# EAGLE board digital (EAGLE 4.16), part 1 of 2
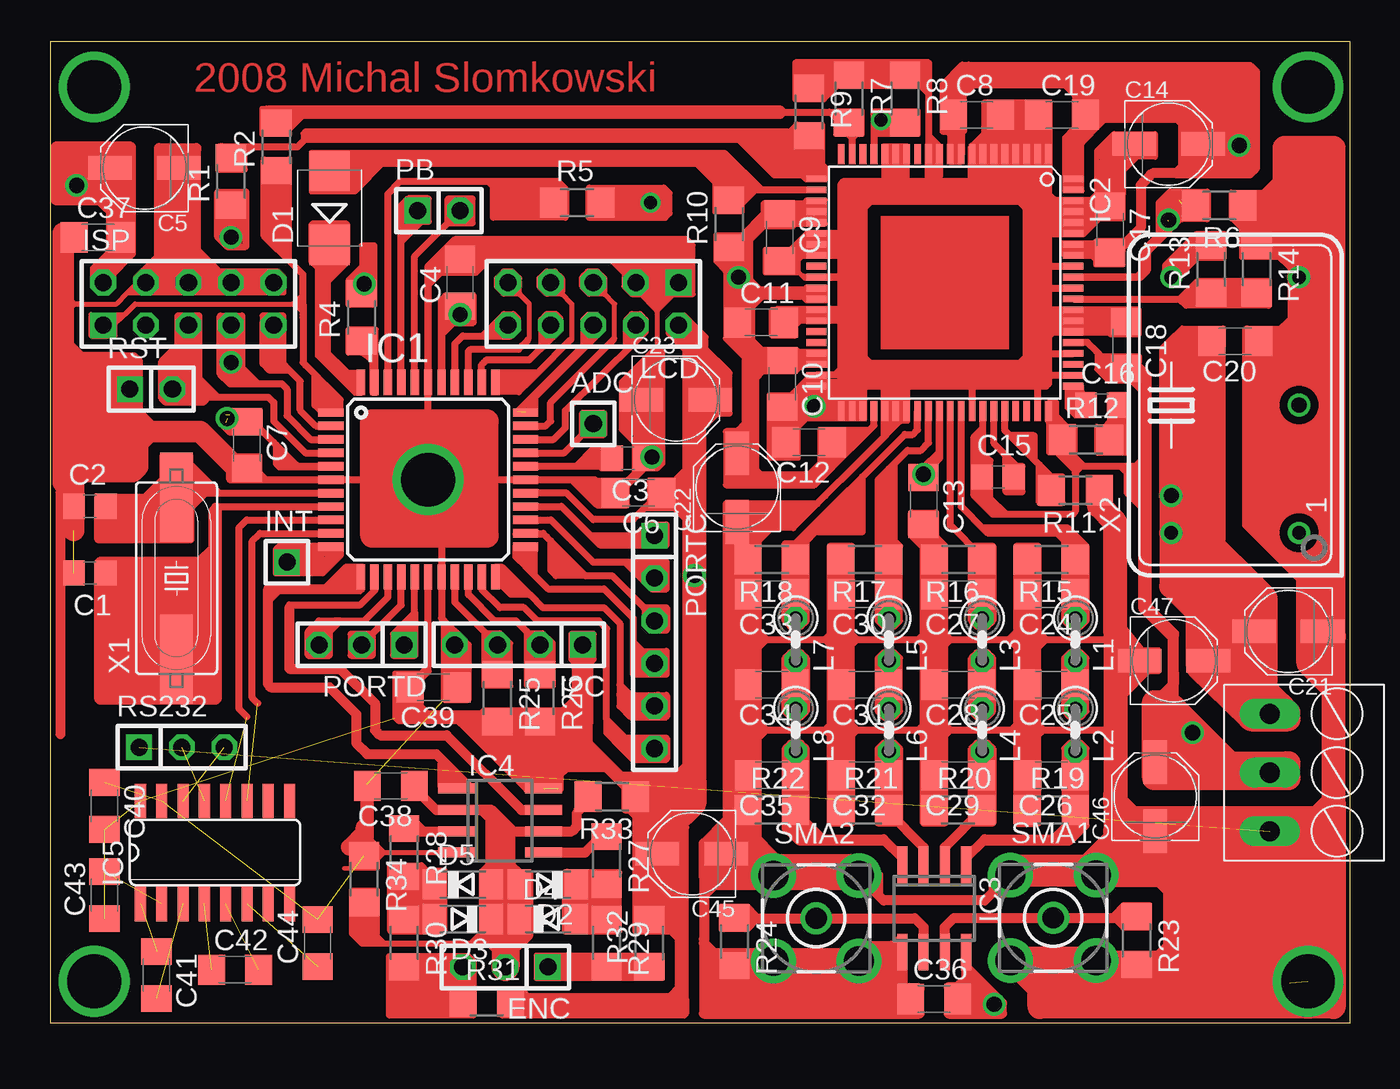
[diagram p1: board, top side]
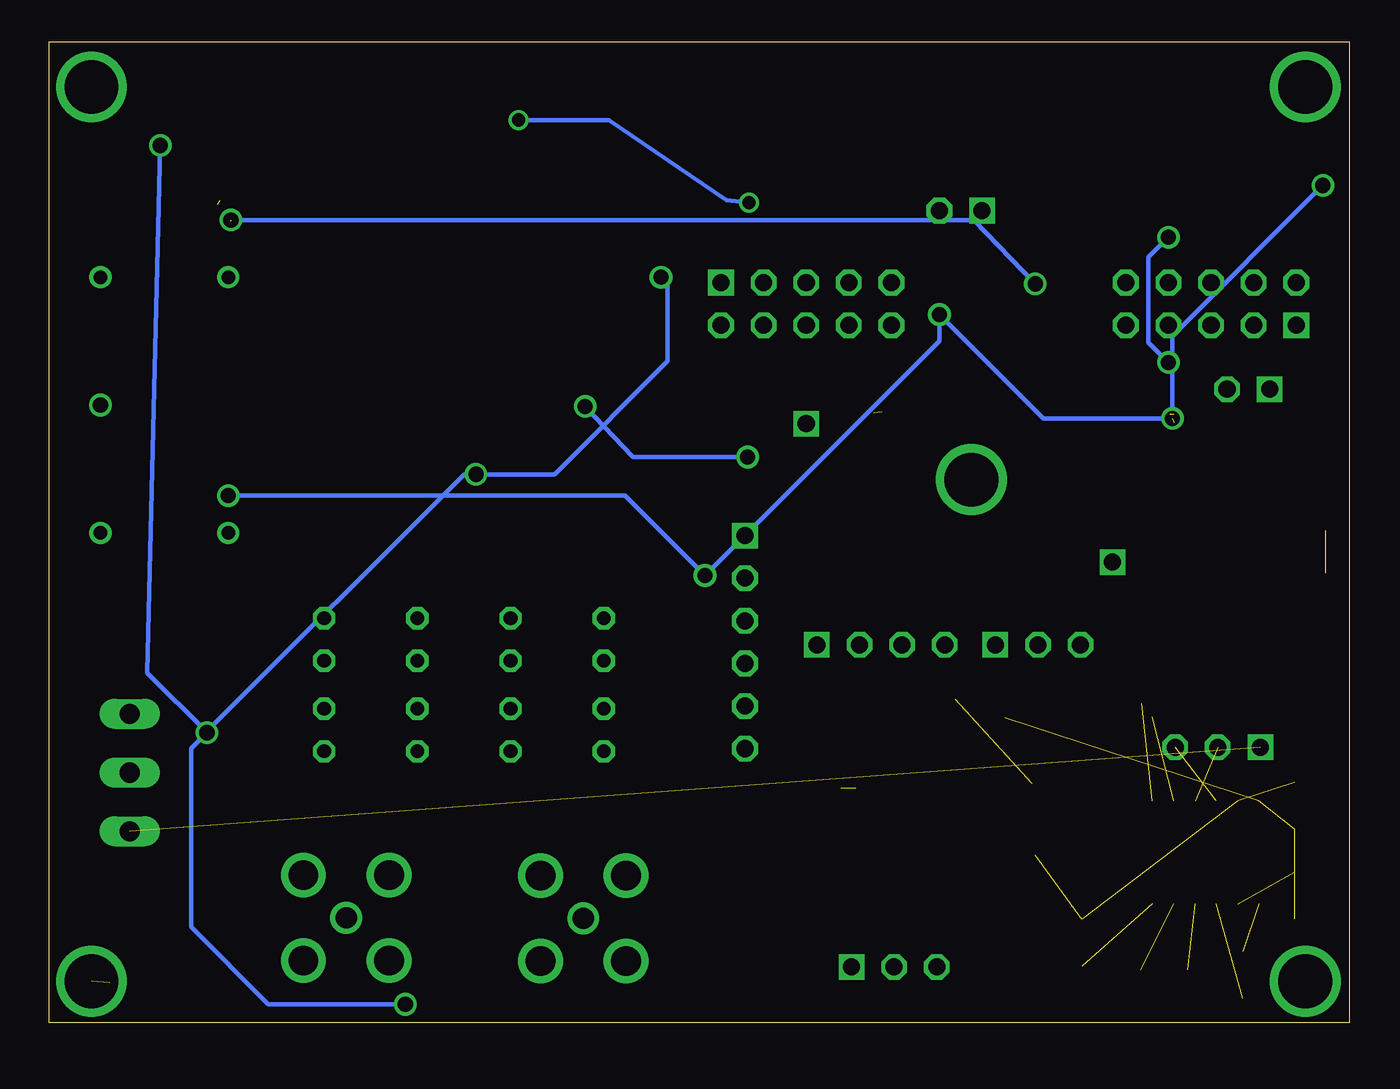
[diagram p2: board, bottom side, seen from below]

Size 77.51 x 58.47 mm. Coordinates in mm from the lower left corner, seen from the top.
Outline: 0,0 77.51,0 77.51,58.47 0,58.47 0,0
Copper layers (1*16): Top 0.035mm / dielectric 1.5mm / Bottom 0.035mm
Design rules "default": minimum track width 10mil, minimum drill 24mil, track to track 8mil, track to pad 8mil, pad to pad 8mil, via to via 8mil, smd to smd 8mil, copper to edge 40mil, drill to drill 8mil, minimum pad ring 10mil, minimum via ring 8mil, stop-mask expansion 4mil, vias tented up to drill 0mil, thermal gap 10mil

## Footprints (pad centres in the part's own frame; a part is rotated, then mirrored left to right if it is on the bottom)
1X01 = drill 1.016 square: 1 0,0
C0805 = smd 1.3 x 1.5: 1 -0.95,0; 2 0.95,0
C1206 = smd 1.6 x 1.8: 1 -1.4,0; 2 1.4,0
PANASONIC_C = smd 2.6 x 1.4: + 2.05,0; - -2.05,0
SMB = smd 2.4 x 2.4: A 2.2,0; C -2.2,0
SOD80C = smd 1.4 x 1.8: A 1.7,0; C -1.7,0
1X03 = drill 1.016 square: 1 -2.54,0 | drill 1.016 octagon: 2 0,0; 3 2.54,0
1X04 = drill 1.016 square: 1 -3.81,0 | drill 1.016 octagon: 2 -1.27,0; 3 1.27,0; 4 3.81,0
TQFP44 = smd 1.5 x 0.5: 1 -5.8,4; 2 -5.8,3.2; 3 -5.8,2.4; 4 -5.8,1.6; 5 -5.8,0.8; 6 -5.8,0; 7 -5.8,-0.8; 8 -5.8,-1.6; 9 -5.8,-2.4; 10 -5.8,-3.2; 11 -5.8,-4; 23 5.8,-4; 24 5.8,-3.2; 25 5.8,-2.4; 26 5.8,-1.6; 27 5.8,-0.8; 28 5.8,0; 29 5.8,0.8; 30 5.8,1.6; 31 5.8,2.4; 32 5.8,3.2; 33 5.8,4 | smd 0.5 x 1.5: 12 -4,-5.8; 13 -3.2,-5.8; 14 -2.4,-5.8; 15 -1.6,-5.8; 16 -0.8,-5.8; 17 0,-5.8; 18 0.8,-5.8; 19 1.6,-5.8; 20 2.4,-5.8; 21 3.2,-5.8; 22 4,-5.8; 34 4,5.8; 35 3.2,5.8; 36 2.4,5.8; 37 1.6,5.8; 38 0.8,5.8; 39 0,5.8; 40 -0.8,5.8; 41 -1.6,5.8; 42 -2.4,5.8; 43 -3.2,5.8; 44 -4,5.8
TQFP80-917 = smd 1.2 x 0.4: 1 -7.65,4.905; 2 -7.65,4.255; 3 -7.65,3.605; 4 -7.65,2.955; 5 -7.65,2.305; 6 -7.65,1.655; 7 -7.65,1.005; 8 -7.65,0.355; 9 -7.65,-0.295; 10 -7.65,-0.945; 11 -7.65,-1.595; 12 -7.65,-2.245; 13 -7.65,-2.895; 14 -7.65,-3.545; 15 -7.65,-4.195; 16 -7.65,-4.845; 17 -7.65,-5.495; 18 -7.65,-6.145; 19 -7.65,-6.795; 20 -7.65,-7.445; 41 7.65,-7.445; 42 7.65,-6.795; 43 7.65,-6.145; 44 7.65,-5.495; 45 7.65,-4.845; 46 7.65,-4.195; 47 7.65,-3.545; 48 7.65,-2.895; 49 7.65,-2.245; 50 7.65,-1.595; 51 7.65,-0.945; 52 7.65,-0.295; 53 7.65,0.355; 54 7.65,1.005; 55 7.65,1.655; 56 7.65,2.305; 57 7.65,2.955; 58 7.65,3.605; 59 7.65,4.255; 60 7.65,4.905 | smd 0.4 x 1.2: 21 -6.175,-8.92; 22 -5.525,-8.92; 23 -4.875,-8.92; 24 -4.225,-8.92; 25 -3.575,-8.92; 26 -2.925,-8.92; 27 -2.275,-8.92; 28 -1.625,-8.92; 29 -0.975,-8.92; 30 -0.325,-8.92; 31 0.325,-8.92; 32 0.975,-8.92; 33 1.625,-8.92; 34 2.275,-8.92; 35 2.925,-8.92; 36 3.575,-8.92; 37 4.225,-8.92; 38 4.875,-8.92; 39 5.525,-8.92; 40 6.175,-8.92; 61 6.175,6.38; 62 5.525,6.38; 63 4.875,6.38; 64 4.225,6.38; 65 3.575,6.38; 66 2.925,6.38; 67 2.275,6.38; 68 1.625,6.38; 69 0.975,6.38; 70 0.325,6.38; 71 -0.325,6.38; 72 -0.975,6.38; 73 -1.625,6.38; 74 -2.275,6.38; 75 -2.925,6.38; 76 -3.575,6.38; 77 -4.225,6.38; 78 -4.875,6.38; 79 -5.525,6.38; 80 -6.175,6.38
SO08 = smd 0.6 x 2.2: 1 -1.905,-2.6; 2 -0.635,-2.6; 3 0.635,-2.6; 4 1.905,-2.6; 5 1.905,2.6; 6 0.635,2.6; 7 -0.635,2.6; 8 -1.905,2.6
SO16 = smd 0.66 x 2.032: 1 -4.445,-3.073; 2 -3.175,-3.073; 3 -1.905,-3.073; 4 -0.635,-3.073; 5 0.635,-3.073; 6 1.905,-3.073; 7 3.175,-3.073; 8 4.445,-3.073; 9 4.445,3.073; 10 3.175,3.073; 11 1.905,3.073; 12 0.635,3.073; 13 -0.635,3.073; 14 -1.905,3.073; 15 -3.175,3.073; 16 -4.445,3.073
2X05 = drill 1.016 square: 1 -5.08,-1.27 | drill 1.016 octagon: 2 -5.08,1.27; 3 -2.54,-1.27; 4 -2.54,1.27; 5 0,-1.27; 6 0,1.27; 7 2.54,-1.27; 8 2.54,1.27; 9 5.08,-1.27; 10 5.08,1.27
0207/2V = drill 0.813 octagon: 1 -1.27,0; 2 1.27,0
1X02 = drill 1.016 square: 1 -1.27,0 | drill 1.016 octagon: 2 1.27,0
1X06 = drill 1.016 square: 1 -6.35,0 | drill 1.016 octagon: 2 -3.81,0; 3 -1.27,0; 4 1.27,0; 5 3.81,0; 6 6.35,0
R1206 = smd 1.6 x 1.803: 1 -1.422,0; 2 1.422,0
BU-SMA-V = drill 1.27 round: 1 0,0 | drill 1.778 round: 2 -2.55,2.55; 3 2.55,2.55; 4 2.55,-2.55; 5 -2.55,-2.55
RIACON-3 = drill 1.2 long: P$1 0,-3.5; P$2 0,0; P$3 0,3.5
HC49UP = smd 5.334 x 1.93: 1 -4.826,0; 2 4.826,0
DIL14S = drill 0.813 round: 1 -7.62,-3.81; 7 7.62,-3.81; 8 7.62,3.81; 14 -7.62,3.81

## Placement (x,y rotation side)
ADC  [1X01]  32.38,35.71 0 top
C1  22p  [C0805]  2.38,26.82 180 top
C2  22p  [C0805]  2.38,30.79 0 top
C3  100n  [C0805]  34.44,33.65 180 top
C4  [C1206]  24.44,44.13 90 top
C5  47u  [PANASONIC_C]  5.63,50.95 180 top
C6  [C1206]  35.08,31.59 180 top
C7  [C1206]  11.74,34.44 270 top
C8  100n  [C1206]  55.24,54.13 0 top
C9  [C1206]  43.49,46.83 270 top
C10  [C1206]  43.65,38.09 270 top
C11  [C1206]  42.38,41.75 0 top
C12  [C1206]  45.24,34.6 180 top
C13  [C1206]  52.07,31.11 270 top
C14  47u  [PANASONIC_C]  66.67,52.38 0 top
C15  10n  [C0805]  56.51,32.54 0 top
C16  10n  [C0805]  62.7,36.82 0 top
C17  [C1206]  63.18,47.3 270 top
C18  [C1206]  64.13,40.4 270 top
C19  [C1206]  60.32,54.13 0 top
C20  100n  [C1206]  70.64,40.63 180 top
C21  47u  [PANASONIC_C]  73.81,23.33 180 top
C22  47u  [PANASONIC_C]  40.95,31.9 90 top
C23  47u  [PANASONIC_C]  37.3,37.14 0 top
C24  10p  [C1206]  59.68,25.55 180 top
C25  33p  [C1206]  59.68,20.15 180 top
C26  10p  [C1206]  59.68,14.76 180 top
C27  10p  [C1206]  54.13,25.55 180 top
C28  33p  [C1206]  54.13,20.16 180 top
C29  10p  [C1206]  54.13,14.76 180 top
C30  10p  [C1206]  48.57,25.55 180 top
C31  33p  [C1206]  48.57,20.15 180 top
C32  10p  [C1206]  48.57,14.76 180 top
C33  10p  [C1206]  43.02,25.55 180 top
C34  33p  [C1206]  43.02,20.15 180 top
C35  10p  [C1206]  43.02,14.76 180 top
C36  100n  [C1206]  52.7,1.42 0 top
C37  100n  [C1206]  2.85,46.82 0 top
C38  100n  [C1206]  20.31,14.12 180 top
C39  100n  [C1206]  22.85,20 180 top
C40  100n  [C1206]  3.25,12.93 270 top
C41  1u  [C1206]  6.34,2.85 270 top
C42  1u  [C1206]  11.03,3.17 0 top
C43  1u  [C1206]  3.25,7.61 90 top
C44  1u  [C1206]  15.95,4.76 90 top
C45  47u  [PANASONIC_C]  38.25,10.07 180 top
C46  47u  [PANASONIC_C]  65.88,13.49 90 top
C47  47u  [PANASONIC_C]  66.99,21.58 0 top
D1  [SMB]  16.66,48.57 90 top
D2  [SOD80C]  29.68,8.25 180 top
D3  [SOD80C]  24.6,6.19 180 top
D4  [SOD80C]  29.68,6.19 0 top
D5  [SOD80C]  24.6,8.25 0 top
ENC  [1X03]  27.14,3.33 180 top
I2C  [1X04]  27.93,22.54 180 top
IC1  MEGA32-A  [TQFP44]  22.54,32.38 0 top
IC2  AD9854  [TQFP80-917]  54.6,44.13 270 top
IC3  FIN1028  [SO08]  52.7,6.82 180 top
IC4  LM358D  [SO08]  26.82,12.06 270 top
IC5  MAX232  [SO16]  9.84,10.15 0 top
INT  [1X01]  14.12,27.46 0 top
ISP  [2X05]  8.25,42.86 0 top
L1  1u  [0207/2V]  61.11,22.85 270 top
L2  1u  [0207/2V]  61.11,17.46 270 top
L3  1u  [0207/2V]  55.56,22.85 270 top
L4  1u  [0207/2V]  55.56,17.46 270 top
L5  1u  [0207/2V]  50,22.85 270 top
L6  1u  [0207/2V]  50,17.46 270 top
L7  1u  [0207/2V]  44.44,22.85 270 top
L8  1u  [0207/2V]  44.44,17.46 270 top
LCD  [2X05]  32.38,42.86 180 top
PB  [1X02]  23.17,48.41 0 top
PORTC  [1X06]  36.03,22.69 270 top
PORTD  [1X03]  18.57,22.54 180 top
R1  [R1206]  10.79,50.16 90 top
R2  [R1206]  13.49,52.22 90 top
R4  [R1206]  18.57,42.06 90 top
R5  [R1206]  31.43,48.89 0 top
R6  [R1206]  69.69,48.73 180 top
R7  [R1206]  47.62,55.08 270 top
R8  [R1206]  50.95,55.08 270 top
R9  [R1206]  45.24,54.29 270 top
R10  [R1206]  40.48,47.62 90 top
R11  3k9  [R1206]  61.11,31.74 180 top
R12  1k3  [R1206]  61.75,34.76 0 top
R13  [R1206]  69.21,44.92 90 top
R14  [R1206]  71.91,44.92 270 top
R15  [R1206]  59.68,27.62 180 top
R16  [R1206]  54.13,27.62 180 top
R17  [R1206]  48.57,27.62 180 top
R18  [R1206]  43.02,27.62 180 top
R19  200  [R1206]  59.68,12.69 0 top
R20  200  [R1206]  54.13,12.69 0 top
R21  200  [R1206]  48.57,12.69 0 top
R22  200  [R1206]  43.02,12.69 0 top
R23  100k  [R1206]  64.77,4.92 270 top
R24  100k  [R1206]  40.79,4.84 270 top
R25  [R1206]  26.66,19.36 270 top
R26  4k7  [R1206]  29.2,19.36 270 top
R27  4k7  [R1206]  33.17,9.68 270 top
R28  4k7  [R1206]  21.11,10.15 270 top
R29  4k7  [R1206]  33.17,4.76 270 top
R30  4k7  [R1206]  21.11,4.76 270 top
R31  1M  [R1206]  26.03,1.26 0 top
R32  1M  [R1206]  35.71,4.76 90 top
R33  4k7  [R1206]  33.49,13.49 180 top
R34  2k2  [R1206]  18.73,8.57 270 top
RS232  [1X03]  7.85,16.42 0 top
RST  [1X02]  6.03,37.78 0 top
SMA1  [BU-SMA-V]  59.8,6.26 0 top
SMA2  [BU-SMA-V]  45.67,6.23 0 top
U$2  RIACON-3  [RIACON-3]  72.7,14.92 180 top
X1  16MHz  [HC49UP]  7.54,26.5 90 top
X2  [DIL14S]  70.64,36.82 90 top

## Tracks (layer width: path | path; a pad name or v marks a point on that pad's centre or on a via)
GND  (1 unrouted)
N$1
  Top 0.406: R9.2 45.4,52.86 45.69,52.89 IC2.21 | 15.39,52.86 14.76,52.22 11.98,52.22 | R1.2 10.16,52.22 10.31,52.22 | 10.31,52.22 11.98,52.22 | 10.31,52.22 10.08,52.22 10.08,50.87 11.58,50.87 11.58,51.83 11.98,52.22
  Top 0.813: R9.2 15.4,52.86 15.39,52.86
N$2
  Top 1.27: 72.46,48.41 72.54,48.41 73.58,47.38
N$3
  Top 0.406: R13.1 69.05,43.49 68.71,43.15 IC2.69
  Top 1.422: R14.2 71.43,43.49 R14.2 R13.1
N$4
  Top 0.406: IC1.44 18.01,38.18 17.46,38.73
  Top 0.61: 17.62,47.46 17.62,45.4 16.35,44.13
  Top 0.813: 17.46,38.73 16.35,39.84 16.35,44.13 16.35,45.4 16.03,45.71 D1.C
N$5
  Top 0.406: R10.2 41.11,49.05 41.72,49.65 IC2.22
  Top 0.813: 41.11,49.05 41.11,50.63 40.32,51.43 17.3,51.43 16.66,50.79 D1.A
N$6
  Top 1.27: R12.2 63.18,34.6 63.65,34.6 C16.2
N$7  (via drill 0.9)  (2 unrouted)
  Top 0.254: R4.2 18.5,43.48 18.49,43.49 18.97,43.97 v18.73,44.05
  Top 0.406: R6.2 68.18,48.65 67.3,48.65 67.3,48.17 65.16,46.03 65.16,44.84 64.77,44.45 IC2.71 65.01,44.45 65.4,44.84 65.4,45.95 67.46,48.02 67.46,48.81 v66.67,47.86
  Top 0.61: R4.2 18.57,43.57 18.49,43.65 19.04,44.21 19.04,44.36
  Top 0.813: 19.04,44.36 19.04,44.68
  Top 1.016: 67.3,49.05 66.99,49.05 66.91,48.97 | 66.67,47.78 66.67,48.73
  Bottom 0.254: v66.67,47.86 22.38,47.86 v18.73,44.05
N$8
  Top 1.016: X2.8 66.83,44.52 68.5,46.19 69.21,46.19 69.29,46.27 R13.2
N$9
  Top 0.61: 3.96,47.46 3.96,48.02 2.93,49.05 0.31,49.05 0.31,52.22 4.84,52.22 4.84,45.87 3.49,44.52
N$10
  Top 0.305: 17.77,44.21 17.77,42.78 19.36,42.78 19.36,46.35 18.57,46.35 18.57,45.08 | 17.77,44.21 17.77,44.28 | 17.77,44.28 18.49,44.84 18.41,44.84 18.57,45 18.57,45.08 | 17.77,44.21 17.77,44.28 | 17.77,44.28 18.57,45.08
N$11
  Top 0.61: R27.1 32.7,11.58 33.33,11.58 31.9,10.15 IC4.5
N$12
  Top 0.406: 59.69,32.54 | R11.2 59.69,32.54 | IC2.56 56.91,35.31 59.69,32.54
N$13
  Top 1.27: 0.79,32.22 0.79,47.06
N$14
  Top 0.406: IC2.55 56.26,34.53 57.62,33.17 57.62,32.7 C15.2 | C15.2 | C15.2
N$15
  Top 1.27: 55.56,20.15 L3.2 | 55.56,20.15 | 55.56,20.15 | C28.1 55.56,20.15 | 55.56,20.15 L4.1
N$16
  Top 0.61: R28.1 21.27,11.42 IC4.3
N$17
  Top 0.406: X1.2 7.62,32.85 7.62,31.58 7.78,31.58 IC1.7
  Top 1.27: C2.2 7.62,30.79 7.62,31.58 | 7.62,31.58
N$18
  Top 0.406: IC1.8 9.83,30.78 9.84,30.47
  Top 0.813: 7.46,26.82 C1.1 | 7.46,26.82 9.2,26.82 9.84,27.46 9.84,27.62 | 9.84,27.62 9.84,28.25 | 9.84,28.25 9.84,30.47 | 7.46,26.82 7.38,26.82 5.31,26.43 X1.1 | 9.84,27.62 9.84,19.36 3.01,19.36 3.01,27.38 8.96,27.38 9.84,28.25
N$19  (1 unrouted)
  Top 0.406: IC1.10 12.51,29.18 12.06,28.73 12.06,19.36 12.38,19.04
N$20  (1 unrouted)
  Top 0.406: IC1.9 11.72,29.98 11.27,29.52 11.27,18.73 11.74,18.25
N$21
  Top 0.406: C3.2 33.33,33.17 33.02,33.18 IC1.29
N$23
  Top 0.406: IC1.19 24.14,25.06 I2C.3
  Top 1.422: R25.1 I2C.3
N$24  (via drill 0.8)
  Top 0.406: IC2.17 49.11,54.27 49.53,53.17 49.53,53.65 | R8.2 50.8,53.66 50.8,53.65 49.53,53.65 | v49.53,53.81 49.53,53.65
  Top 1.422: R5.2 v35.79,48.89
  Bottom 0.254: v35.79,48.89 37.14,49.05 44.13,53.81 v49.53,53.81
N$25
  Top 0.406: R4.1 18.42,40.8 18.41,40.79 19.34,39.87 IC1.43
N$26
  Top 0.406: IC1.42 20.14,49.43 20.87,50.16 25.87,50.16 | 25.87,50.16 26.11,50.16 27.06,49.21 28.73,49.21 29.05,48.89 R5.1 | 30.71,49.68 26.59,49.68 | 30.71,49.68 30.71,48.02 26.43,48.02 26.43,49.76 | 25.87,50.16 30.24,50.16 30.71,49.68
N$27
  Top 0.406: C16.1 61.75,37.14 60.98,37.91 IC2.61
N$28
  Top 0.406: 58.73,22.22 59.37,22.85 58.89,23.33 58.89,28.41 57.62,28.41 57.62,23.33 57.15,22.85 57.78,22.22
N$29
  Top 0.406: R16.1 55.55,27.77 55.56,27.77 53.66,29.67 IC2.51
  Top 1.27: C27.1 55.53,25.42 55.56,25.39 L3.1
  Top 1.422: R16.1 55.55,25.56 55.56,25.55 | C27.1 55.56,25.55 | 55.56,25.55
N$30
  Top 0.406: IC2.49 52.36,34.58 51.91,34.12 51.11,34.12 50,33.01 50,32.85
  Top 0.61: R17.1 49.99,27.46 50,27.46 50,32.85
  Top 1.27: 50,25.55 L5.1
  Top 1.422: 50,27.46 50,25.55 | C30.1 50,25.55 | 50,25.55
N$31
  Top 0.406: IC2.48 51.71,35.36 51.43,35.08 50.95,35.08 44.45,28.57 44.45,27.46 44.44,27.46 R18.1
  Top 1.27: L7.1 44.45,25.55
  Top 1.422: 44.45,25.55 | 44.45,25.55 C33.1 | 44.45,27.46 44.45,25.55
N$32
  Top 1.27: 61.11,20.15 L2.1 | 61.11,20.15 L1.2
  Top 1.422: 61.11,20.15 | C25.1 61.11,20.15 | 61.11,20.15
N$33
  Top 0.61: R19.2 61.42,12.53 59.84,10.95 55.72,10.95 54.61,9.84 | 54.61,9.84 | IC3.1 54.61,9.84
  Top 1.27: 61.11,14.76 L2.2
  Top 1.422: 61.11,14.76 | 61.11,14.76 | 61.11,14.76 C26.1 | R19.2 61.11,14.75 61.11,14.76
N$34
  Top 1.016: L6.1 50,20.08 49.92,20.15 C31.1 50,20.15 | 50,20.15 L5.2 | 50,20.15
N$35
  Top 0.61: IC3.3 52.07,10.47 49.99,12.54 R21.2
  Top 1.27: 50,14.76 L6.2
  Top 1.422: 50,14.76 | 50,14.76 | 50,14.76 C32.1 | R21.2 49.99,14.75 50,14.76
N$36
  Top 0.61: R20.2 53.34,10.47 IC3.2
  Top 1.27: 55.56,14.6 L4.2
  Top 1.422: R20.2 55.55,14.59 55.56,14.6 | 55.56,14.6 55.53,14.63 C29.1 | 55.56,14.6
N$37
  Top 1.27: 44.45,20.15 L7.2 | 44.45,20.15 | C34.1 44.45,20.15 | 44.45,20.15 L8.1 | 44.45,20.15
N$38
  Top 0.61: 53.81,6.18 53.34,5.71 IC3.7 | 53.81,6.18 53.89,6.26 | 53.81,6.18 | 53.89,6.26 SMA1.1 64.68,6.26 R23.1 | 53.81,6.18 53.89,6.26
N$39
  Top 0.61: 51.59,6.18 52.07,5.71 IC3.6 52.07,4.12 | 51.59,6.18 51.54,6.23 | 51.54,6.23 SMA2.1 40.83,6.23 R24.1 | 51.54,6.23 51.59,6.18 | R24.1 | R24.1
N$40
  Top 0.406: 31.19,32.3 | 31.19,32.3 32.62,30.87 34.36,30.87 34.36,31.98
N$41
  Top 0.305: 59.45,49.44 59.45,49.37 59.76,49.05 | 59.45,49.52 | 59.45,49.52 59.92,49.05
  Top 0.406: 59.69,49.05 59.76,49.05 59.92,49.05 62.07,49.05 62.7,49.68
N$42
  Top 0.813: 31.9,32.14 32.7,31.35 32.7,31.98
N$43
  Top 1.422: R29.1 31.43,6.18 | 31.43,6.18 | 31.43,6.18 D4.A | 31.43,6.18 31.38,6.23 D2.C 31.38,8.36 31.91,8.26 R27.2
N$44
  Top 1.27: R30.1 | R30.1 D3.A 22.9,8.2 22.86,8.25 | R30.1 | R28.2 22.05,8.73 22.86,8.25 | 22.86,8.25 D5.C
N$47
  Top 1.422: ENC.1 33.09,3.33 33.1,3.33 R29.2 33.18,3.33 R32.1
N$48
  Top 1.27: R30.2 ENC.3 24.6,1.34 24.61,1.34 R31.1
N$49
  Top 0.61: 34.05,14.68 36.27,14.68 | 34.05,14.68 33.81,14.68 | 32.06,17.93 32.06,16.66 34.05,14.68
N$50
  Top 0.406: IC1.23 28.34,27.21 28.89,26.66 | 28.89,26.66 29.68,25.87 33.02,25.87 34.76,24.12 34.76,22.7 | PORTC.4 | 34.76,22.7 35.32,22.14 | 35.32,22.14 PORTC.4 | 28.89,26.66 28.89,28.41 | 35.32,22.14 36.75,22.14 36.75,20.79 34.76,20.79 34.76,22.7
N$51
  Top 0.406: IC1.13 19.34,26.53 19.36,26.5 19.36,25.79 18.49,24.92 14.28,24.92 14.28,24.76
  Top 0.61: IC4.7 28.09,12.69 23.65,17.14 19.68,17.14 19.36,17.46 19.36,19.04 17.3,21.11 14.28,21.11 14.28,24.76
N$52
  Top 0.406: IC1.12 18.48,26.58 18.09,26.19 18.09,25.87
  Top 0.61: 23.49,13.96 IC4.1 | 23.49,13.96 | 23.49,13.96 23.49,15.55 23.01,16.03 18.89,16.03 18.25,16.66 18.25,18.41 16.66,20 13.17,20 13.01,20.15 13.01,25.87 18.09,25.87
N$53
  Top 0.406: IC1.24 29.39,29.18 29.6,28.97 | 29.6,28.97 29.84,28.73 29.84,26.98 30.16,26.66 31.9,26.66 | 36.03,24.12 | 36.03,24.12 PORTC.3 | 31.9,26.66 33.49,26.66 35.4,24.76 | 35.4,24.76 36.03,24.12 | 29.6,28.97 | 29.6,28.97 31.9,26.66 | 35.4,24.76 35.48,24.76 | 35.48,24.76 36.75,24.76 36.75,23.41 35.79,23.41 35.48,23.73 35.48,24.76
N$54
  Top 0.406: IC1.25 29.86,29.98 32.38,27.46 34.29,27.46 | PORTC.2 35.87,26.5 34.92,27.46 | 34.29,27.46 34.92,27.46 | 34.92,27.46 36.75,27.46 36.75,25.87 35.87,25.87 34.29,27.46
N$55
  Top 0.406: IC1.26 30.49,30.78 32.22,29.04 | 36.19,29.04 | 36.19,29.04 PORTC.1 | 32.22,29.04 34.92,29.04 | 34.92,29.04 36.19,29.04 | 32.22,29.04 32.78,28.49 36.75,28.49 36.75,29.68 35.55,29.68 34.92,29.04
N$56
  Top 0.406: IC1.14 20.14,25.38 18.73,23.96 17.3,23.96 | PORTD.3 16.03,23.01 16.98,23.96 17.22,23.96 | 17.22,23.96 17.3,23.96 | 17.22,23.96 16.03,23.96 15.39,23.33 15.39,21.9 16.66,21.9 16.66,23.33 17.3,23.96
N$57
  Top 0.406: PORTD.2 | IC1.15 20.94,24.9 19.2,23.17 | 19.2,23.17 PORTD.2 | 19.2,23.17 19.2,21.9 17.93,21.9 17.93,23.17 19.2,23.17
N$58
  Top 0.406: PORTD.1 21.74,22.54 21.74,22.7 21.74,21.91 IC1.16
N$59
  Top 0.406: ADC.1 | IC1.30 30.65,33.98 31.74,35.08 | 31.74,35.08 ADC.1 | 31.74,35.08 31.74,36.35 33.02,36.35 33.02,35.08 31.74,35.08
N$60
  Top 0.406: IC1.11 15.04,28.38 INT.1
N$61
  Top 0.406: IC1.40 21.74,45.71 22.86,46.82 | PB.2 | 22.86,46.82 | 22.86,46.82 23.73,47.7 | 23.73,47.7 PB.2 | 23.73,47.7 23.73,49.13 25.16,49.13 25.16,47.7 23.73,47.7
N$62
  Top 0.406: IC1.41 20.94,47.21 21.9,48.17 21.9,48.25 PB.1
N$63  (1 unrouted)
N$64  (1 unrouted)
N$65  (1 unrouted)
N$66  (1 unrouted)
N$67  (1 unrouted)
N$68  (1 unrouted)
N$69  (1 unrouted)
N$70  (1 unrouted)
N$71  (via drill 3.2 pad 3.81)
  other vias: 2.63,2.47
N$72  (via drill 3.2 pad 3.81)  (1 unrouted)
  Top 3.81: 60.32,2.38 73.89,2.38
  other vias: 74.98,2.47
N$73  (via drill 3.2 pad 3.81)
  other vias: 74.98,55.78
N$74  (via drill 3.2 pad 3.81)
  other vias: 2.63,55.78
N$75
  Top 0.305: 62.38,35.55 62.86,35.55 63.18,35.87 63.18,37.46 64.29,37.46 64.29,33.97 62.38,33.97 62.38,35.55
N$76
  Top 0.305: 64.13,34.12 64.13,34.28
N$77
  Top 0.406: 61.27,37.94 61.43,37.94 61.43,37.62 61.59,37.46
N$78
  Top 0.305: 61.75,37.46 62.23,37.46 62.23,36.19 61.11,36.19 60.64,36.66 60.64,37.94
N$79
  Top 0.406: 27.78,29.12 29.36,29.12
N$80
  Top 0.406: 59.84,36.82 59.84,35.87 60.16,35.55
N$81
  Top 0.61: 60.96,36.66 60.96,37.78
N$82
  Top 0.305: 51.11,37.78 51.11,35.87 50.64,35.87 49.68,35.87 49.68,37.78 | 49.68,34.92 49.68,36.82
  Top 0.406: 49.68,34.92 50.64,35.87
N$83
  Top 0.61: 50.16,36.19 50.16,37.78
N$84
  Top 0.61: 50.8,36.19 50.8,37.78
N$85
  Top 0.305: 44.6,39.84 44.6,39.36 | 44.6,39.84
  Top 0.406: 46.19,39.84 45.4,39.84
  Top 0.61: 46.19,39.36 46.19,39.84 44.6,39.84 | 44.6,39.36 44.29,39.05 | 44.6,39.84 | 44.6,39.84 44.45,40 42.38,40 41.75,40.63 41.75,43.33
N$86
  Top 0.61: 41.59,42.86 41.59,42.7 41.43,42.54
N$87
  Top 0.254: 48.57,37.78 48.57,36.03 44.92,36.03
N$88
  Top 0.61: 44.45,35.55 44.92,36.03
N$89
  Top 0.813: 45.4,42.06 44.6,42.06 44.13,41.59
N$90
  Top 0.406: 43.02,33.81 43.02,36.03
N$91
  Top 0.813: 44.76,36.19 44.76,37.3
N$92
  Top 0.305: 43.18,42.54 43.02,42.54 43.02,40.95 44.45,40.95
N$93
  Top 0.305: 45.16,36.03 45.08,36.03 | 45.16,36.03 48.41,36.03 | 45.16,36.03 45.16,37.78
N$94
  Top 0.254: 61.91,46.51 60.8,46.51 | 61.91,46.51 62.38,46.51 | 60.32,46.51 | 60.32,46.51 61.91,46.51 | 60.32,46.51 62.23,46.51 62.38,46.67 64.13,46.67 | 60.32,46.51 60.32,45.87 60.48,45.71
  Top 0.305: 60.48,45.71 | 60.48,45.71 61.91,45.71 | 60.48,45.71 60.48,46.35
N$95
  Top 0.305: 62.54,47.94 63.97,47.94 63.97,49.37 62.38,49.37 62.07,49.05 59.84,49.05 | 62.54,47.94 | 59.53,46.98 61.59,46.98 62.54,47.94
N$97
  Top 0.305: 45.24,38.25 46.98,38.25
N$98
  Top 0.305: 44.45,40.95 44.45,41.59
N$99
  Top 0.406: 56.19,18.57 55.88,18.25 55.24,18.25 54.92,18.57 54.92,21.74 55.24,22.06 55.88,22.06 56.19,21.74 56.19,18.57
N$100
  Top 0.406: 60.8,22.06 61.27,22.06 | 60.8,22.06 60.48,21.74 60.48,18.57 60.8,18.25 61.43,18.25 61.75,18.57 61.75,21.74 61.43,22.06 60.8,22.06
N$101
  Top 0.406: 50.32,22.06 50.64,21.74 50.64,18.57 50.32,18.25 49.68,18.25 49.37,18.57 49.37,21.74 49.68,22.06 50.32,22.06
N$102
  Top 0.406: 44.13,18.25 44.76,18.25 45.08,18.57 45.08,21.74 44.76,22.06 44.13,22.06 43.81,21.74 43.81,18.57 44.13,18.25 | 44.13,18.25
N$103
  Top 1.422: 26.03,29.04 26.03,35.87 19.2,35.87 19.2,29.04 26.03,29.04
N$104
  Top 0.406: 60,29.2 60.48,28.73 60.48,23.96 60.8,23.65 61.43,23.65 61.75,23.96 61.75,28.41 60.64,29.52 55.56,29.52
N$105
  Top 0.406: 60.8,27.93 60.8,28.73 60.32,29.2 55.88,29.2 55.72,29.36 | IC2.52 54.31,30.77 55.72,29.36 | 56.03,29.36 55.72,29.36 | 55.72,29.36
  Top 0.61: 56.03,29.36 60.48,29.36 61.11,28.73 R15.1 | R15.1 | R15.1
  Top 0.813: R15.1 | R15.1
  Top 1.27: 61.11,25.71 61.09,25.68 C24.1 | 61.11,25.71 L1.1 | 61.11,25.71
  Top 1.422: 61.11,25.39 61.09,25.42 C24.1 61.11,25.55 61.11,25.56 R15.1 | 61.11,25.39
N$106
  Top 0.406: 54.92,28.41 56.19,28.41 56.19,23.96 55.88,23.65 55.24,23.65 54.92,23.96 54.92,28.41
N$107
  Top 0.406: 50.16,33.17 49.37,32.38 49.37,23.96 49.68,23.65 50.32,23.65 50.64,23.96 50.64,28.41 50.32,28.73 50.32,33.33
N$108
  Top 0.406: 49.68,28.41 49.68,32.54
N$109
  Top 0.305: 50.32,35.71 50.16,35.71 50,35.55
N$110
  Top 0.406: 48.41,32.54 48.41,29.28 45.64,29.28 45.08,28.73 45.08,23.96 44.76,23.65 44.13,23.65 43.81,23.96 43.81,28.57 44.76,28.57
N$111
  Top 0.813: 45.87,29.52 48.1,31.74
N$112
  Top 0.813: 48.1,30.95 | 46.67,29.52 48.1,30.95
N$113
  Top 0.813: 47.46,29.52 48.1,30.16
N$114
  Top 0.813: 47.94,29.52 48.1,29.52
N$115
  Top 0.406: 16.43,38.01 | 16.43,38.01 17.3,37.14 17.3,36.35 16.27,36.35 15.79,36.82 15.79,38.57
N$116
  Top 0.406: 42.22,23.33 42.22,28.89 | 42.22,22.38 42.22,23.33 | 42.22,17.93 42.22,22.38 | 42.22,16.98 42.22,17.93 | 42.22,9.92 42.22,16.98 | 42.22,23.33 | 42.22,23.33 42.7,22.85 42.22,22.38 | 42.7,17.46 41.59,17.46 | 42.7,17.46 46.19,17.46 | 46.19,17.46 48.1,17.46 | 48.1,17.46 51.75,17.46 | 51.75,17.46 53.65,17.46 | 53.65,17.46 57.3,17.46 | 57.3,17.46 59.21,17.46 | 59.21,17.46 63.02,17.46 | 42.22,17.93 | 42.7,17.46 42.22,17.93 | 46.19,17.46 46.67,17.93 | 42.22,16.98 42.7,17.46 | 46.19,17.46 | 46.19,17.46 46.67,16.98 | 47.62,17.93 | 48.1,17.46 47.62,17.93 | 48.1,17.46 47.78,17.14 | 47.78,17.14 47.62,16.98 | 51.75,17.46 52.22,17.93 | 51.75,17.46 52.22,16.98 | 53.65,17.46 53.18,17.93 | 53.65,17.46 | 53.65,17.46 53.18,16.98 | 58.73,17.93 59.21,17.46 | 59.21,17.46 58.73,16.98 | 57.3,17.46 57.78,17.93 | 57.3,17.46 | 57.3,17.46 57.78,16.98 | 47.78,17.14 47.78,16.66 | 47.78,16.66 47.78,11.9 46.51,11.9 46.51,22.54 46.19,22.85 46.67,23.33 | 47.78,16.66 47.78,22.7
N$117
  Top 0.305: 63.97,49.37 63.97,50.79 64.77,51.59 65.88,51.59 65.88,53.02 63.42,53.02 62.38,51.98 62.38,48.89 61.59,48.89
N$118
  Top 0.406: 53.65,22.85 53.18,23.33 | 53.65,22.85 | 53.18,22.38 53.65,22.85
N$119
  Top 0.406: 52.38,23.33 52.22,23.33 51.75,22.85 52.07,22.54 | 52.07,22.54 52.22,22.38 | 52.07,22.54 52.07,11.9 53.34,11.9 53.34,22.85
N$120
  Top 0.406: 47.62,23.33 | 47.62,23.33 48.1,22.85 47.62,22.38
N$121
  Top 0.61: 63.34,52.54 63.34,52.38 62.7,51.75
N$122
  Top 0.406: 57.3,22.85 | 57.78,22.38 57.3,22.85
N$123
  Top 0.406: 44.76,16.66 44.6,16.66 | 44.76,16.66 45.08,16.34 45.08,11.9 | 44.76,16.66 44.13,16.66 43.81,16.34 43.81,11.58 44.6,10.79 49.68,10.79
  Top 0.61: R22.2 44.44,12.54 45.08,11.9 45.87,11.11 | 45.87,11.11 | 45.87,11.11 46.03,10.95 49.68,10.95 50.8,9.84 IC3.4
  Top 1.27: 44.45,14.76 L8.2
  Top 1.422: R22.2 44.44,14.75 44.45,14.76 | 44.45,14.76 | 44.45,14.76 C35.1 | 44.45,14.76
N$124
  Top 0.813: 61.75,47.62 62.07,47.94 62.07,48.41
N$125
  Top 0.406: 58.89,22.54 58.89,11.9 57.62,11.9 57.62,22.54
N$126
  Top 0.406: 55.72,10.79 60.8,10.79 61.75,11.74 61.75,16.34 61.43,16.66 60.8,16.66 60.48,16.34 60.48,11.58
N$127
  Top 0.813: 61.27,11.74 61.11,11.74 60.48,11.11
N$128
  Top 0.406: 54.92,11.9 56.19,11.9 56.19,16.34 55.88,16.66 55.24,16.66 54.92,16.34 54.92,12.22
N$129
  Top 0.406: 50.64,12.06 50.64,16.34 50.32,16.66 49.68,16.66 49.37,16.34 49.37,11.9 50.48,11.9
N$130
  Top 0.813: 44.29,12.06 44.29,11.9 44.92,11.27 45.24,11.27 45.4,11.11
N$131
  Top 0.305: 46.03,49.05 45.08,49.05 44.92,48.89
N$132
  Top 0.254: 68.34,45.55 70,45.55 70,47.06 68.34,47.06 66.43,45.16 66.43,44.36
N$133
  Top 0.305: 40.16,45.08 40.16,45.24 40,45.4
N$134
  Top 0.61: 40.64,32.38 41.59,32.38
N$135
  Top 0.254: 45.87,33.49 45.87,35.39 48.89,35.39
N$136
  Top 0.254: 46.98,33.65 46.83,33.65
N$137
  Top 0.406: 48.41,35.24 47.62,34.44 47.62,35.24 48.1,35.24 47.78,34.92
N$138
  Top 0.305: 46.35,39.2 46.19,39.2 | 46.35,39.2 46.35,40 44.68,40 | 46.35,39.2 44.84,39.2 44.45,38.81 42.54,38.81 42.14,38.41
N$139
  Top 0.305: 42.3,38.73 42.3,38.97 42.78,38.97
N$140
  Top 0.305: 46.67,38.65 45.16,38.65 45.16,38.41 44.13,37.38
N$141
  Top 0.305: 46.19,49.05 46.19,47.62 44.45,47.62 44.29,47.46 42.54,47.46
N$142
  Top 0.254: 46.98,47.14 45.16,47.14 44.13,46.11 42.62,46.11 42.62,44.68 44.6,44.68 | 44.6,44.68 44.68,44.68 45,44.36 46.98,44.36 | 44.6,44.68 44.6,45.48 44.84,45.71
N$143
  Top 0.305: 44.92,44.52 46.98,44.52
N$144
  Top 0.813: 44.37,45.95 46.83,45.95
N$145
  Top 0.406: 44.6,46.35 44.68,46.35 45.16,46.82
N$146
  Top 0.406: 45.24,46.75 46.98,46.75
N$147
  Top 0.406: 45,46.51 45,46.35
N$148
  Top 0.254: 44.45,45.55 44.45,44.76
N$149
  Top 0.254: 44.84,43.25 45.08,43.02 46.27,43.02 46.27,43.89 45.08,43.89 44.92,43.73
N$150
  Top 0.254: 46.11,43.17 46.11,43.65
N$151
  Top 0.406: 42.46,43.33 41.83,42.7
N$152
  Top 0.406: 28.33,27.22 27.78,27.77 27.78,28.41
N$153
  Top 0.406: 28.65,25.47 26.98,27.14 26.51,27.14
N$154
  Top 0.406: 36.27,19.52 36.19,19.52 | 36.27,19.52 36.75,19.52 36.75,18.25 34.6,18.25 33.97,18.88 33.97,19.6 | IC1.22 26.54,26.47 26.98,26.03 | 26.98,26.03 27.46,25.55 28.57,25.55 29.36,24.76 33.02,24.76 33.97,23.81 33.97,20.15 | 33.97,20.15 33.97,19.6 | 33.97,19.6 33.97,19.52 34.6,18.88 35.87,18.88 PORTC.5 | 26.98,26.03 26.51,26.03 | 36.27,19.52 34.6,19.52 33.97,20.15
N$155
  Top 0.406: IC1.21 25.74,25.84 26.82,24.76 28.25,24.76 29.05,23.96 32.7,23.96 33.02,23.65 | 33.02,23.65 | 33.02,23.65 33.17,23.49 33.17,18.09 | 33.17,18.09 33.17,17.3 34.05,16.42 | 34.05,16.42 34.13,16.34 PORTC.6 | PORTC.6 | 34.05,16.42 34.76,15.71 36.75,15.71 36.75,16.98 34.29,16.98 33.17,18.09
N$156
  Top 0.406: 33.41,17.46 | 33.41,17.46 34.29,16.58 36.51,16.58
N$157
  Top 0.813: 34.68,16.27 36.43,16.27
N$158
  Top 0.813: 36.51,19.12 34.6,19.12 34.29,19.44
N$159
  Top 0.813: 36.43,18.57 34.76,18.57 34.52,18.81
N$160
  Top 0.813: 35.16,21.9 36.43,21.9
N$161
  Top 0.813: 35,21.27 36.43,21.27
N$162
  Top 0.813: 35.87,24.44 36.35,24.44
N$163
  Top 0.813: 35.95,23.89 36.35,23.89
N$164
  Top 0.813: 35,27.22 35.08,27.22 36.03,26.27 36.43,26.27 36.43,26.98 35.79,26.98
N$165
  Top 0.813: 35.71,29.2 36.35,29.2
N$166
  Top 0.813: 32.86,28.81 36.51,28.81
N$167
  Top 0.813: 26.82,26.66 27.06,26.66 27.86,25.87
N$168
  Top 0.813: 28.17,28.09 28.17,27.85
N$169
  Top 0.813: 28.65,28.09 28.65,27.46
N$170
  Top 0.813: 30.16,28.01 30.16,27.06
N$171
  Top 0.813: 30.79,27.46 30.79,27.06
N$172
  Top 0.813: 31.27,26.98 31.27,26.9
N$173
  Top 1.016: 41.75,30.55 44.76,30.55
N$174
  Top 1.016: 41.75,29.92 44.05,29.92
N$175
  Top 1.016: 42.3,29.28 42.22,29.28 41.75,28.81
N$176
  Top 1.016: 40.79,28.01 40.79,12.69 40.71,12.61
N$177
  Top 0.61: 34.36,14.36 35.63,14.36 35.71,14.44
N$178
  Top 0.61: 32.54,15.63 32.54,15.71 32.14,16.11
N$179
  Top 0.813: 25.95,18.41 31.19,18.41
N$180
  Top 1.422: 25.63,17.77 28.81,14.6
N$181
  Top 1.422: 29.76,14.52 29.76,17.14
N$182
  Top 1.422: 30.87,17.3 30.87,15.79
N$183
  Top 1.422: 27.62,17.14 28.97,15.79
N$184
  Top 1.422: 28.89,17.38 28.89,16.9
N$188
  Top 0.254: 16.11,28.49 13.65,28.49 13.41,28.25 13.41,26.74 16.27,26.74 17.38,27.85 17.38,28.49
N$189
  Top 0.254: 18.65,27.22 17.62,27.22 16.43,26.03
N$190
  Top 0.254: 18.65,26.9 18.65,26.03 18.65,25.95 18.41,25.71
  Top 0.305: 18.65,27.14 18.65,26.03 18.65,25.87 18.49,25.71 13.65,25.71 13.17,25.23
N$191
  Top 0.61: 17.14,28.17 16.27,27.3
N$192
  Top 0.61: 16.82,28.09 16.11,28.09
N$193
  Top 0.61: 17.77,26.98 | 17.77,26.98 16.9,26.11
N$194
  Top 0.61: 18.17,26.9 18.17,26.74 17.54,26.11
N$195
  Top 0.406: 21.74,21.9 20.47,21.9 20.47,23.17 21.74,24.44 21.74,21.9 | 21.74,21.9 21.74,25.95
N$196
  Top 0.406: 21.43,22.06 21.43,23.81
N$197
  Top 0.813: 21.11,23.41 21.11,23.25 20.87,23.01 20.87,22.3
N$198
  Top 0.813: 16.35,23.57 | 15.87,23.09 16.35,23.57
N$199
  Top 0.813: 16.35,23.09 16.35,22.46
N$200
  Top 0.813: 15.79,22.7 15.79,22.14
N$202
  Top 0.813: 23.73,20.71 23.73,23.25
N$203
  Top 0.813: 24.2,22.77 24.2,20.87
N$204
  Top 0.813: 24.6,22.22 24.6,20.95
N$205  (via drill 0.9)  (6 unrouted)
  Top 0.254: 22.38,20.87 20.55,20.87 20.55,18.17 20.79,17.93 24.52,17.93 | C7.1 10.74,35.84 v10.55,36.03 | C4.1 24.44,42.78 v24.44,42.22 23.34,41.12 IC1.38 | C5.+ 3.65,50.95 3.73,50.87 2.77,49.92 v1.58,49.92 | v66.83,31.43
  Top 0.406: IC1.5 13.64,33.18 13.49,33.33 13.49,34.44 12.06,35.87 C7.1 | C39.2 21.74,20.15 22.54,20.95 IC1.17 | IC1.27 30.8,31.58 32.38,30 34.76,30 36.35,31.58 36.19,31.58 C6.1 | C4.1 24.44,42.86 23.34,41.75 IC1.38
  Top 0.61: 24.36,18.09 24.52,17.93 28.49,13.96 30.32,13.96 30.32,14.84 30.71,15.23 33.33,15.23 | R32.2 35.71,6.42 37.38,8.09 37.78,11.74 37.78,1.42 | 37.78,1.42 37.78,0.95 37.22,0.95 27.22,0.95 27.06,1.1 27.22,1.26 R31.2 | 37.78,1.42 37.78,0.55 37.46,0.55 | 37.46,0.55 37.3,0.55 | 37.46,0.55 26.98,0.55 | 10.71,35.47 10.71,36.27 | 10.47,35.79 10.47,36.27
  Top 0.813: C39.2 21.45,18.54 21.74,18.25 26.03,18.25 26.35,17.93 R25.2 | 31.74,17.93 31.74,15.87 32.22,15.39 33.17,15.39 33.33,15.23 34.91,13.65 R33.1
  Top 1.27: I2C.1 31.74,17.93 R26.2 | R26.2 | R25.2 R26.2 | 35.71,10 36.03,10 | 36.03,10 C45.+ | 36.03,10 | 38.33,15.55 38.33,15.15 37.46,14.28
  Top 1.422: R32.2 35.71,10 35.71,13.49 35.55,13.49 | R33.1 35.08,13.49 35.55,13.49 | C6.1 38.1,31.58 38.41,31.58 | 38.41,14.44 38.41,14.28 37.46,14.28 36.35,14.28 35.55,13.49 | 38.41,14.44 v38.41,26.66 38.41,31.58 | 69.05,40.63 | 69.05,40.63 C20.2 | 69.05,40.63 67.46,40.63 66.83,40 v66.83,31.43 X2.14 66.83,26.03 68.73,24.12 68.73,23.33 | LCD.2 | 38.41,31.58 38.41,37.14 | 38.41,37.14 38.41,40.63 LCD.2 | C23.+ 38.41,37.14 | 68.73,21.58 68.57,21.42 71.58,18.42 U$2.P$1 | 68.73,21.58 C47.+ 68.73,21.58 | 68.73,21.58 | 68.73,23.33 68.73,21.58 | 68.73,23.33 68.89,23.33 | 68.89,23.33 C21.+ | 68.89,23.33 | ISP.2 3.17,44.84 4.28,45.95 4.28,46.67 4.2,46.75 4.25,46.8 C37.2 4.25,50.43 3.73,50.95 C5.+ | 38.41,14.44 38.41,13.09 36.9,11.58 36.9,8.41
  Bottom 0.254: v66.83,31.43 43.18,31.43 v38.41,26.66 24.44,40.63 v24.44,42.22 18.25,36.03 v10.55,36.03 10.55,40.95 v1.58,49.92
N$206
  Top 0.254: 22.14,20.39 22.14,18.88 22.54,18.49
N$207
  Top 0.813: 20.87,19.12 20.87,18.49 21.11,18.25
N$208
  Top 0.305: 21.9,19.04 21.9,18.81 22.06,18.65
N$209
  Top 0.305: 22.54,21.27 | 21.98,20.71 22.54,21.27
N$210
  Top 0.305: 25.95,23.25 26.82,23.25 27.46,22.62 27.46,20.08 25.87,20.08 25.87,23.25
N$211
  Top 0.305: 28.57,23.25 29.36,23.25 30,22.62 30,20.08 28.41,20.08 28.41,23.33
  Top 0.406: IC1.20 24.94,25.53 26.51,23.96 27.78,23.96 28.41,23.33 I2C.2
  Top 1.422: I2C.2 R26.1
N$213
  Top 0.406: 30.79,32.38 32.46,32.38 32.54,32.3 34.52,32.3
N$214
  Top 0.254: 32.78,33.09 32.86,33.01 34.05,33.01 34.05,34.28 32.38,34.28 31.27,33.17
N$215
  Top 0.61: 32.54,34.05 | 31.82,33.33 32.54,34.05
N$216
  Top 0.61: 32.46,33.33 32.94,33.81
N$217
  Top 0.406: IC1.2 15.85,35.58 14.92,36.51 14.92,38.25 14.28,38.89 | 14.28,38.89 13.97,38.89 | 13.97,38.89 13.81,38.89 13.33,39.36 ISP.9 | ISP.9 | 14.28,38.89 13.89,39.28 13.89,42.14 12.7,42.14 12.7,41.74 | 12.7,41.74 12.77,41.67 | 12.7,41.74 12.7,39.28 13.09,38.89 13.97,38.89
N$218  (via drill 0.9)
  Top 0.406: IC1.3 15.53,34.78 14.12,36.19 14.12,37.78 13.81,38.09 12.38,38.09 | 11.66,38.09 11.27,38.09 10.79,38.57 10.79,38.81 v10.79,39.36 ISP.7 | 11.66,38.09 12.38,38.09 | ISP.7 | 12.38,38.09 11.43,39.05 11.43,42.14 10.16,42.14 10.16,38.65 10.71,38.09 11.66,38.09
  Top 1.422: v10.79,46.82 R1.1 | v10.79,46.82
  Bottom 0.254: v10.79,46.82 11.98,45.63 11.98,40.55 v10.79,39.36
N$219
  Top 0.61: 11.11,38.73 11.19,38.73 11.66,38.25
N$220
  Top 0.406: IC1.4 15.22,33.98 13.33,35.87 13.33,36.98 13.01,37.3 10,37.3 | 9.44,37.3 8.73,37.3 8.25,37.78 | 9.44,37.3 10,37.3 | ISP.5 | 8.25,37.78 ISP.5 | RST.2 8.25,37.78 | 8.25,37.78 | 10,37.3 8.89,38.41 8.89,42.14 7.62,42.14 7.62,40.4 6.66,39.44 6.66,37.22 6.9,36.98 9.12,36.98 9.44,37.3
N$221
  Top 0.813: 8.89,38.09 8.89,38.01 9.36,37.54
N$222
  Top 0.813: 7.69,37.38 7.69,39.92
N$223
  Top 0.813: 7.14,37.3 7.14,39.52
N$225
  Top 0.813: 39.13,4.04 50.4,4.04
N$226
  Top 0.305: 34.84,32.78 34.84,34.76
N$227
  Top 1.016: 34.6,38.01 36.11,39.52
N$228
  Top 1.016: 35.87,38.41 35.87,38.33 35.32,37.78
N$229
  Top 1.016: 36.03,33.41 36.03,36.35
N$230
  Top 1.016: 34.52,35.47 34.52,36.59
N$232
  Top 0.61: 0.63,17.22 0.63,31.58
N$234
  Top 0.406: 24.52,3.96 24.6,3.96 | 24.52,3.96 20.24,3.96 20.24,0.47 25.24,0.47 25.24,3.64 24.92,3.96 24.52,3.96
N$235
  Top 0.406: 18.25,6.34 18.25,5.23 18.57,4.92
N$236
  Top 0.406: 19.28,5.07 19.44,4.92
N$237
  Top 0.406: 20.31,5.47 20.31,9.36 22.14,9.36 22.46,9.04 23.49,9.04 23.49,5.47 20.31,5.47
N$238
  Top 0.406: 30.87,8.96 30.79,8.96 | 30.87,8.96 33.89,8.96 33.89,5.47 30.71,5.47 30.71,8.96 30.87,8.96
N$239
  Top 0.61: 26.27,8.88 26.27,12.38
N$240
  Top 0.305: 19.44,37.54 19.44,41.35 17.77,41.35 17.77,39.92 18.57,39.92 19.2,39.44 19.2,37.54 19.44,37.54
N$241
  Top 0.254: 19.92,4.76 19.52,5.15 19.52,7.93 17.93,7.93 17.93,5.31 18.57,4.68 26.11,4.68 26.43,4.36
  Top 0.305: 18.89,5.23 19.36,4.76 19.92,4.76 25.16,4.76 27.14,4.76 | 27.14,4.76
  Top 0.406: 26.27,9.44 26.19,9.44 25.79,9.04 25.79,5.39 25.16,4.76 | 27.7,4.12 27.7,4.28 28.57,5.15 28.57,8.96 28.01,8.96 27.46,9.52
  Top 0.61: 25.63,12.69 26.35,12.69 27.46,11.58 | 25.63,12.69 IC4.2 23.01,12.69 22.22,13.49 | 27.46,11.58 27.62,11.42 29.68,11.42 | 27.78,8.25 27.46,8.25 27.46,9.52 27.46,11.58 | C38.1 21.71,13.99 22.22,13.49 | 22.22,13.49 | 32.54,13.96 R33.2 32.07,13.18 31.43,12.54 31.43,11.74 31.11,11.42 29.68,11.42 | 29.68,11.42 | 29.68,11.42 IC4.6 | 25.63,12.69 25.71,12.69 26.35,12.06
  Top 1.016: 28.09,6.34 27.98,6.23 D4.C | 28.09,6.34 26.98,6.34 26.82,6.18 D3.C | D5.A 27.78,8.25 D2.A 28.09,8.25 28.09,6.34 | R34.2 18.89,6.98 18.89,5.23
  Top 1.676: ENC.2 27.14,4.76 27.14,6.18 26.98,6.34
N$242
  Top 0.61: 28.33,5.31 27.93,4.92
N$243
  Top 0.61: 25.71,5.07 26.74,5.07
N$244
  Top 0.61: 23.57,15.47 | 23.57,15.47 25,14.04 23.41,14.04 23.41,15.47
N$245
  Top 0.61: 23.81,14.76 23.81,14.6 24.12,14.28
N$246
  Top 0.254: 33.89,4.04 33.97,4.04 | 33.89,4.04 28.97,4.04 28.97,2.61 36.51,2.61 36.51,4.04 33.89,4.04
N$247
  Top 0.254: 29.28,3.96 | 29.28,3.96 29.13,3.8 29.13,2.77 29.2,2.69
N$248
  Top 0.305: 18.73,39.92 18.89,39.92 19.12,39.68
N$249
  Top 0.813: 18.97,46.03 18.97,44.84 18.33,44.21
N$250
  Top 0.254: 14.04,54.52 12.62,54.52 12.62,52.94 14.28,52.94 14.28,53.25 15.08,54.05
N$251
  Top 0.305: 14.68,53.89 14.6,53.89 14.36,53.65
N$252
  Top 0.305: 40.95,52.7 43.18,50.48 44.84,50.48 45.08,50.24 46.19,50.24 46.19,51.03 46.03,51.19 46.03,53.57 44.52,53.57 44.13,53.17 15.63,53.17 | 15.63,53.17 | 15.63,53.17 14.76,52.3 | 15.63,53.17 15.24,53.17 15.08,53.02 15.08,52.54
N$253
  Top 0.305: 45.95,50.4 45.95,51.11
N$254
  Top 0.61: 43.1,50.95 41.51,52.54
N$255
  Top 0.61: 42.14,52.54 | 42.14,52.54 43.02,51.67 43.02,52.54 42.78,52.54
N$256
  Top 0.254: 42.46,49.68 40.24,51.91 15.55,51.91 15.55,49.52 18.17,49.52 19.92,51.27
N$257
  Top 0.254: 42.06,49.6 | 41.27,48.81 42.06,49.6 | 41.27,48.81 40.87,48.41 | 41.27,48.81 41.27,48.33 39.6,48.33 39.6,50.08 38.33,51.35
N$258
  Top 0.305: 67.15,20.87 67.15,20.23 | 67.15,20.87 67.15,23.25 65.48,24.92 | 67.15,19.36 67.15,20.87
N$259
  Top 0.406: 66.83,19.04 66.83,23.01
N$262
  Top 0.61: 28.09,1.82 28.41,1.5 36.98,1.5 37.62,2.14
N$263
  Top 0.406: 34.29,13.96 34.29,12.69 35.16,12.69
N$264
  Top 0.406: 34.92,12.61 34.92,5.47 37.54,5.47
N$265
  Top 0.406: 37.78,2.45 37.78,2.22 36.9,1.34
N$266
  Top 0.406: 34.52,12.85 34.52,12.69 35,12.22
N$267
  Top 0.406: 67.38,43.09 67.7,42.78 72.62,42.78 72.62,44.21 68.42,44.21 67.38,43.17
N$268
  Top 0.61: 68.02,43.33 68.42,43.73
N$269  (via drill 0.9)
  other vias: 74.45,36.82
N$270
  Top 0.406: 36.83,5.95 36.83,5.63 37.54,4.92
  Top 0.61: 37.54,7.69 37.54,4.92 37.54,1.74
N$271
  Top 0.61: 28.17,1.34 37.46,1.34
N$272
  Top 0.254: 41.59,6.98 41.59,5.55 | 41.59,5.55 40,5.55 40,6.98 41.59,6.98 | 41.59,6.98 | 41.59,6.98 42.14,6.42 | 41.59,5.55 42.14,6.11
N$273
  Top 0.254: 63.5,6.11 63.97,5.63 65.56,5.63 65.56,7.06 63.97,7.06 63.34,6.42
N$274
  Top 0.254: 63.97,5.87 63.81,6.03
N$275
  Top 0.254: 63.89,6.82 63.89,6.74 63.73,6.58
N$276
  Top 0.254: 41.75,6.74 41.75,6.5
N$277
  Top 0.254: 41.75,6.03 41.75,5.87
N$278
  Top 0.61: 50.16,4.6 50.72,4.6 | 50.16,4.6 47.86,4.6 47.38,4.12 | 50.16,4.6 50.32,4.6 50.72,4.99
N$279
  Top 1.93: 39.68,8.88 48.26,8.88
N$280
  Top 1.93: 41.43,11.74 41.43,11.03
N$281
  Top 1.27: 39.68,10.87 39.68,10.79 39.52,10.63
N$282
  Top 1.016: 55,2.38 55,1.98 55.72,1.26
N$283
  Top 1.676: 57.15,3.72 62.86,3.72 63.1,3.49 68.5,3.49
N$284
  Top 1.676: 57.38,9.2 61.91,9.2 63.34,10.63
N$285
  Top 1.422: 66.03,8.8 62.3,8.8 | 66.03,8.8 66.67,8.8 67.07,8.41 67.07,4.44 66.03,3.41 | 66.03,8.8 66.27,8.8 66.99,8.09
N$286
  Top 1.778: 63.89,10.23 66.43,10.23 66.67,10
N$287
  Top 1.778: 59.29,2.45 66.51,2.45 66.59,2.38
N$288
  Top 0.406: 67.46,47.94 68.97,47.94 68.97,49.52 66.75,49.52 66.11,48.89 66.11,47.06
N$289
  Top 0.61: 71.83,51.03 71.83,56.59
N$290
  Top 0.61: 71.83,56.67 71.51,56.98 54.68,56.98
N$291
  Top 0.254: 53.41,53.25 53.65,53.02
  Top 0.305: 53.65,53.02 53.49,53.17 53.41,53.25 53.73,53.33 53.18,53.33 53.18,53.57 | 53.18,53.57 53.18,55.95 54.37,57.14 54.76,57.14 | 53.18,53.57 53.18,53.1 54.29,53.1
  Top 0.406: 53.65,53.02 53.65,51.35 54.29,51.35
N$292
  Top 0.406: 54.45,55.32 54.45,53.17 54.29,53.02
N$293
  Top 0.813: 53.97,51.59 53.97,52.94 53.57,53.33
N$294
  Top 0.61: 54.92,56.83 54.53,56.83 53.49,55.79 53.49,55
N$295
  Top 0.61: 67.54,50.95 67.54,53.73
N$296
  Top 0.61: 60.88,56.75 61.19,56.43
N$297
  Top 0.305: 61.51,52.46 61.51,49.6 60.48,49.6 60.48,52.78 61.03,53.33
N$298
  Top 0.406: 59.53,50.24 59.53,54.84 55.72,54.84 55.72,53.02 55,52.3
N$299
  Top 0.406: 54.92,50.24 54.92,52.22
N$300
  Top 0.61: 55.32,50.4 55.32,52.46
N$301
  Top 0.406: 52.7,50.32 52.7,52.22
N$302
  Top 0.254: 51.11,52.3 49.76,52.3
N$303
  Top 0.254: 49.68,51.75 49.68,52.3
N$304
  Top 0.254: 49.29,52.94 51.75,52.94 51.75,54.37 49.05,54.37 49.05,52.86
N$305
  Top 0.305: 59.45,42.54 64.92,42.54 64.92,41.03 63.18,41.03 63.1,41.11 62.07,41.11 | 62.07,41.11 61.99,41.11 61.91,41.19 | 62.07,41.11 59.76,41.11 59.61,40.95
N$306
  Top 0.305: 64.92,39.36 64.92,39.76 62.62,39.76
N$307  (via drill 0.9)
  Top 0.254: IC2.31 45.69,43.2 45.72,43.17 45.69,43.15 IC2.32 45.69,43.44 45.64,43.49 | 66.99,17.44 67.05,17.44 67.07,17.46 67.23,17.3 v68.1,17.3 | 40.79,45.08 41.11,45.08 41.03,45 v41.03,44.44 | IC2.79 60.96,49.68 60.96,50.24
  Top 0.305: 65.08,37.62 64.45,38.25 63.1,38.25 62.38,38.97 62.38,40 | 44.92,48.89 42.54,48.89 42.54,48.25 41.27,46.98 39.68,46.98 39.68,45.4 40.32,44.76 | 59.53,36.98 60,36.98 60,36.19 60.64,35.55 61.11,35.55 61.11,33.97 | 61.11,33.97 59.53,33.97 59.53,35.87 | 60.96,34.12 61.11,33.97 | 65.4,33.49 65.24,33.49 | IC2.23 45.64,48.97 45.69,48.92 IC2.24 | 61.59,33.17 61.51,33.17 61.11,32.78
  Top 0.406: 47.78,34.28 45.56,32.06 40.32,32.06 40.32,35.24 40.95,35.24 41.27,35.55 | 41.27,35.55 | 41.27,35.55 41.43,35.71 41.43,39.68 40.32,40.79 40.32,44.76 40.32,46.82 41.51,46.82 41.75,46.82 | 54.29,51.78 IC2.9 54.31,54.74 53.65,54.13 | 54.29,51.78 IC2.10 | 54.29,51.78 54.29,51.75 | 53.65,54.13 | C8.1 53.65,54.13 | R12.1 60.32,35.08 59.53,35.87 59.51,35.89 IC2.60 | 45.69,48.25 IC2.24 45.69,48.38 | 45.69,48.25 IC2.25 | 45.69,48.25 45.72,48.25 | 45.69,39.52 IC2.38 45.69,39.49 45.72,39.52 | 45.69,39.52 IC2.37 | 45.72,39.52 45.69,39.52 | 45.69,48.38 45.72,48.41 | C9.1 45.53,48.23 45.69,48.38 | C10.1 45.59,39.49 45.72,39.52 | IC2.73 60.98,46.22 61.11,46.35 61.06,46.4 IC2.74 63.76,46.4 63.81,46.35 | IC2.80 60.98,50.19 60.96,50.16 60.98,50.13 | 63.5,46.03 | 63.5,46.03 C17.2 | IC2.73 63.22,45.75 63.5,46.03 | C15.1 | C15.1 | 55.61,33.17 55.61,32.59 C15.1 | 55.61,33.17 IC2.54 | 52.22,32.85 53.02,33.65 53.02,36.19 53.01,36.2 IC2.50 53.01,34.04 52.07,33.09 v52.07,32.7 | C12.1 46.67,34.44 46.83,34.28 47.78,34.28 | IC2.44 49.11,35.62 47.82,34.32 | 47.82,34.32 47.78,34.28 | 46.35,34.28 47.14,35.08 | 60.96,34.12 60.96,33.49 61.27,33.17 | 55.61,33.17 55.61,30.9 56.03,30.47 | 56.03,30.47 | 56.03,30.47 56.19,30.31 60.96,30.31 61.11,30.47 61.11,32.78 61.11,32.93 | 61.11,32.93 61.11,33.01 61.27,33.17 | 65.4,33.49 65.4,33.17 65.24,33.17 61.59,33.17 61.27,33.17 | IC2.65 61.83,40.55 62.38,40 62.7,39.68 62.7,39.52 | C18.2 63.18,39.05 62.7,39.52 | 62.7,39.52 62.7,39.36 63.18,38.89 65.08,38.89 65.4,38.57 65.24,38.57 65.24,38.41 | 52.22,32.85 | v52.07,32.7 C13.1 | 52.22,32.85 v52.07,32.7 | 47.82,34.32 47.78,34.36 47.78,34.28 | 47.82,34.32 | IC2.73 63.37,45.75 65,47.38
  Top 0.406: 65,49.92 65,50 65.64,50.63 65.72,50.63 | v70.88,52.3 68.81,52.3 | 61.11,32.93 59.84,34.2 | 64.21,33.09 64.21,31.58 65.24,30.55
  Top 0.61: 41.51,43.41 40.95,42.7 40.95,42.22 40.79,42.06 | 40.79,42.06 C11.1 | 40.79,42.06 | 63.81,46.35 63.97,46.35 64.92,47.3 65,47.38 65,49.92 65.24,50.16 65.4,50.32 65.72,50.63 67.15,50.63 | C14.+ 68.26,52.38 68.81,52.3 67.15,50.63 | C36.2 54.13,1.42 54.61,1.9 54.61,3.57 | 66.83,23.17 | 66.99,18.81 66.99,20.79 | 66.99,20.79 66.99,23.09 66.83,23.17 | 54.61,3.57 IC3.8 | 54.61,3.57 54.61,1.1 v56.27,1.1 | 54.61,3.57 54.61,3.33 56.75,1.18 56.75,0.55 53.57,0.55 53.57,2.14 54.13,2.14 54.53,2.53 | 67.15,50.63 71.51,50.63 71.83,50.95 | 60.98,50.13 60.98,50.21 60.96,50.24 | 66.99,20.79 66.99,20.23 65.96,19.2
  Top 0.813: 41.51,44.21 41.51,46.82 | 41.51,44.21 41.51,43.57 | R10.1 40.64,46.19 41.27,46.51 43.33,48.57 43.49,48.25 C9.1 | C9.1 | 65.24,33.33 65.24,33.17 65.24,30.55 65.24,24.76 66.83,23.17 | 41.75,34.12 41.59,34.12 41.41,33.95 C22.+ | 65.24,33.49 65.24,38.17 | 65.24,38.17 65.24,38.41 | 40.79,43.49 41.83,43.49 | 41.83,43.49 42.22,43.49 | 42.22,43.49 45.64,43.49 | 41.83,43.49 41.19,44.13 | 41.51,44.21 | 42.22,43.49 41.51,44.21 | 65.24,38.17 65.24,38.57 64.69,39.13
  Top 1.016: 46.35,34.28 46.35,33.33 45.4,32.38 42.22,32.38 41.75,32.85 41.75,34.12 41.75,39.52 | 41.75,39.52 41.75,39.84 40.95,40.63 40.95,41.59 40.98,41.62 C11.1 | C10.1 41.78,39.49 41.75,39.52 | C19.2 61.72,53.15 60.96,52.38 | IC2.80 60.98,50.13 60.98,50.03 60.96,50 60.96,52.38 | 60.96,52.38 | 60.96,52.38 62.7,54.13 67.3,54.13 67.78,53.65 | 67.78,53.65 | 67.78,53.65 67.94,53.49 67.94,53.17 68.73,52.38 C14.+ | 60.96,52.38 60.96,52.54 61.43,53.02 61.43,55.4 60.64,56.19 54.92,56.19 54.13,55.4 54.13,54.45 53.84,54.57 C8.1
  Top 1.27: C11.1 40.79,41.93 40.79,42.06 40.79,43.49 40.79,45.08 40.79,45.88 R10.1
  Top 1.422: U$2.P$2 66.19,14.92 66.19,16.66 66.03,16.5 C46.+ 66.99,17.44 66.99,18.81 70.32,15.47 73.73,15.47 73.81,15.39
  Bottom 0.254: v56.27,1.1 64.45,1.1 69.05,5.71 69.05,16.34 v68.1,17.3 | v68.1,17.3 68.18,17.3 52.78,32.7 v52.07,32.7 47.38,32.7 40.64,39.44 40.64,44.05 v41.03,44.44 | v70.88,52.3 71.67,20.87 v68.1,17.3
N$308
  Top 0.406: 64.61,38.33 64.84,38.09
N$309
  Top 0.406: 62.78,39.44 63.34,39.44
N$310
  Top 0.406: 62.54,39.2 62.54,39.13 63.18,38.49
N$311
  Top 0.305: 68.26,46.75 | 66.59,45.08 68.26,46.75
N$312
  Top 0.406: 51.83,56.19 52.07,56.19 52.22,56.03
N$313
  Top 0.61: 51.83,56.91 52.14,56.91
N$314
  Top 1.016: 44.84,56.67 46.98,56.67
N$315
  Top 1.016: 41.51,50.08 41.51,50 41.67,49.84
N$316
  Top 1.016: 40.24,50 38.97,51.27
N$317
  Top 1.016: 40.08,50.79 40.71,50.16
N$318
  Top 0.254: 46.83,54.37 48.41,54.37 48.41,52.94 48.1,52.94 47.86,52.7 47.78,52.7 47.54,52.94 46.83,52.94 46.83,53.89 46.43,54.29
  Top 0.406: IC2.19 47.81,53.62 47.78,53.65 R7.2 47.46,53.66 46.83,54.29 46.43,54.29 43.49,54.29
  Top 0.813: R2.2 | R2.2 | 43.49,54.29 12.93,54.29 R2.2
N$319
  Top 0.305: 72.78,49.52 70.4,49.52 70.4,47.94 70.48,47.94 71.04,47.38 71.04,45.63 73.34,45.63
N$320
  Top 0.406: 71.99,49.29 71.99,48.81
N$321
  Top 0.406: 70.8,47.94 70.8,47.86 71.04,47.62
N$322
  Top 0.254: 63.97,46.11 63.97,45.16 62.3,45.16 62.3,45.48 62.07,45.71
N$323
  Top 1.422: 72.46,23.17 72.46,23.33 | 72.46,23.17 72.46,19.84 73.26,19.04 | 73.26,19.04 73.73,18.57 73.73,18.41 72.7,18.41 | 72.7,18.41 72.62,18.41 72.46,18.57 | 72.7,18.41 71.51,18.17 68.42,21.19 | 72.46,23.17 72.46,25.31 68.42,29.36 | 73.26,19.04 73.81,18.49 73.81,18.09 71.59,18.09
N$324
  Top 1.422: 68.42,21.27 68.42,24.44 68.34,24.52
N$325
  Top 1.422: 69.37,27.14 69.37,40.63
N$326
  Top 0.305: 69.92,40.32 69.92,41.43 67.46,41.43 66.27,40.24
N$327
  Top 1.422: 75.72,21.42 75.72,27.77
N$328
  Top 0.61: 73.34,41.27 71.35,41.27 71.35,29.68 74.92,26.11 74.92,26.66 71.75,29.84
N$329
  Top 1.016: 75.48,43.41 75.48,41.51
N$330
  Top 1.016: 73.58,30.79 73.26,30.47
N$331
  Top 1.016: 72.78,29.68 72.78,29.44
N$332
  Top 1.016: 75.56,31.35 75.56,30.71 75.96,30.31
N$333
  Top 1.016: 75.56,38.49 75.56,38.25 75.88,37.94
N$334
  Top 1.016: 76.19,36.03 76.19,35.95 75.56,35.32
N$335
  Top 1.016: 72.86,35.79 72.94,35.79 73.26,35.47
N$336
  Top 1.016: 73.81,38.81 | 73.02,38.01 73.81,38.81
N$337
  Top 1.016: 18.73,11.66 18.73,11.34 17.85,10.47
N$338
  Top 0.61: 21.58,11.98 21.66,11.98 22.14,11.5
N$339
  Top 0.254: 19.92,10.15 19.52,10.55 | 19.92,10.15 | 19.92,10.15 19.44,9.68
N$340
  Top 0.254: 19.52,9.68 19.52,9.2 17.54,9.2
N$350
  Top 0.61: 8.73,52.06 8.73,46.03 10.23,44.52
N$351
  Top 0.61: 8.73,52.14 6.5,52.14 6.5,45.63 5.23,44.36 5.23,44.05
N$352
  Top 0.61: 13.41,44.68 8.65,44.68 8.57,44.76
N$353
  Top 0.61: 8.89,45.55 8.89,45.08 9.12,44.84
N$354
  Top 0.61: 6.98,45.16 6.58,45.16 6.11,44.68
N$355
  Top 0.406: 10,46.82 10.55,46.27 11.66,46.27 11.66,49.52 10,49.52 10,46.82
N$356
  Top 0.305: ISP.1 3.8,41.59 4.44,42.22 | 4.44,42.22 5.08,42.86 14.44,42.86 | 15.08,42.22 15.08,42.06 | 14.44,42.86 15.08,42.86 | 4.44,42.22 2.46,42.22 2.46,40.95 3.88,40.95 3.88,42.06 3.96,42.06 | 14.44,42.86 14.52,42.86 15,43.33 | 14.44,42.86 14.6,42.86 15,42.46
  Top 0.406: 14.2,45.48 14.2,51.43 12.77,51.43 12.77,46.9 13.49,46.19 | IC1.1 16.74,37.7 15.24,39.2 | 15.08,39.36 15.24,39.2 | 15.08,42.06 15.08,39.36 | 13.49,46.19 R2.1 | 15.24,39.2 | 15.08,39.36 15.08,42.22 15.08,42.86 15.08,44.6 13.81,45.87 13.49,46.19 | 15.08,39.36 15.24,39.2
N$357
  Top 0.406: 13.89,46.03 13.89,50
N$358
  Top 0.61: 13.09,46.82 13.09,50
N$359
  Top 0.305: 3.8,43.89 3.8,44.52 | 3.8,43.89 | 3.8,43.89 3.41,43.49 2.93,43.49 2.54,43.89 2.54,45 3.49,45.95 3.49,48.81
N$360  (via drill 0.9, 3.2)  (5 unrouted)
  Top 0.254: 5.87,43.49 5.71,43.49 | 5.87,43.49 13.97,43.49 13.97,44.44 | 13.97,44.44 | 13.97,44.44 13.57,44.84 13.41,44.84 | 44.6,35.39 44.6,33.65 42.86,33.65 42.86,37.46 44.6,37.46 44.68,37.46 44.76,37.54 | IC2.43 48.44,36.48 48.41,36.51 | IC2.78 61,49 61.3,48.7 C17.1 | 47.14,39.05 46.83,38.73 | 36.51,33.33 36.27,33.33 v35.87,33.73 | v45.56,36.74 45.56,36.66 44.68,37.54 44.76,37.54 | 44.96,37.82 45,37.78 44.76,37.54 | 44.76,37.54 | 4.6,43.49 5.87,43.49
  Top 0.305: 35.4,33.01 36.19,33.01 36.51,33.33 36.51,40 36.19,40.32 | 19.52,10.15 IC4.4 | 19.52,10.15 | R34.1 18.73,10.63 18.89,10.79 | ISP.4 5.23,44.13 4.6,43.49 3.96,42.86 1.74,42.86 | 1.11,42.86 1.74,42.86 | 58.1,50.16 58.1,48.89 | 58.1,48.89 58.1,48.57 | 58.1,48.57 58.1,39.68 | 58.1,39.68 58.1,39.36 | 58.1,39.36 58.1,38.09 | 48.57,39.36 48.57,37.94 | 48.57,39.68 48.57,39.36 | 48.57,48.57 48.57,39.68 | 48.57,48.89 48.57,48.57 | 48.57,48.89 48.57,50.16 | 48.89,48.89 48.57,48.89 | 57.78,48.89 48.89,48.89 | 58.1,48.89 57.78,48.89 | 48.89,39.36 48.57,39.36 | 57.78,39.36 48.89,39.36 | 58.1,39.36 57.78,39.36 | 58.1,39.68 57.78,39.36 | 48.57,39.68 48.89,39.36 | 48.89,48.89 48.57,48.57 | 58.1,48.57 57.78,48.89 | 36.19,42.86 36.19,42.38 | 36.19,40.32 36.19,39.92 | 1.74,42.86 1.27,42.86 | 36.19,40.32 35.87,40 | 35.87,40 | 35.87,40 34.05,38.17 34.05,35.39 34.84,34.6 | 36.19,42.86 | 36.35,43.02 36.19,42.86 | 36.19,42.38 36.19,40.32 | 36.19,42.46 37.14,43.41 38.33,43.41 38.33,46.35 37.94,46.75 24.12,46.75 22.46,45.08 22.46,38.73 | 36.19,42.38 36.19,42.46 | 36.19,42.46 35.16,43.49 | LCD.3
  Top 0.406: 59.51,50.16 IC2.1 | 51.11,50.16 52.38,50.16 | 52.38,50.16 53.02,50.16 | 53.02,50.16 54.92,50.16 | 54.92,50.16 55.88,50.16 | 55.88,50.16 56.19,50.16 | 56.19,50.16 56.83,50.16 | 56.83,50.16 57.46,50.16 | 58.41,50.16 58.1,50.16 57.46,50.16 | 58.41,50.16 58.73,50.16 | 59.51,50.16 58.73,50.16 | IC2.16 49.76,50.16 49.84,50.16 | 50.48,50.16 51.11,50.16 | 49.84,50.16 50.48,50.16 | IC2.14 51.06,50.16 51.11,50.16 | 52.38,50.16 52.36,50.16 IC2.12 52.36,51.77 52.38,51.75 52.38,52.86 | IC2.11 53.01,50.16 53.02,50.16 | IC2.8 54.96,50.16 54.92,50.16 | 55.88,50.16 55.61,50.16 IC2.7 55.61,51.69 55.72,51.59 55.72,54.76 55.72,54.13 C8.2 | IC2.6 56.26,50.16 56.19,50.16 | IC2.5 56.91,50.16 56.83,50.16 | IC2.4 57.56,50.16 57.46,50.16 | IC2.3 58.21,50.16 58.41,50.16 | 58.73,50.16 58.86,50.16 IC2.2 58.86,51.46 58.89,51.43 58.92,51.46 C19.1 | 59.51,50.16 59.53,50.16 59.53,49.05 | IC2.62 59.53,38.6 59.53,38.73 | 59.53,48.41 59.53,49.05 | 59.53,47.62 59.53,48.41 | 59.53,46.98 59.53,47.62 | 59.53,42.54 59.53,43.81 | 59.53,43.81 59.53,45.08 | 59.53,45.08 59.53,46.98 | 59.53,40 59.53,41.27 | 59.53,41.27 59.53,41.9 | 59.53,41.9 59.53,42.54 | 59.53,38.73 59.53,40 | IC2.64 59.53,39.9 59.53,40 | IC2.68 59.53,42.5 59.53,42.54 | IC2.75 59.53,47.05 59.53,46.98 | IC2.76 59.53,47.7 59.53,47.62 | IC2.77 59.53,48.35 59.53,48.41 | IC2.78 59.53,49 59.53,49.05 | 47.14,37.95 IC2.40 45.1,37.95 44.6,37.46 43.84,36.69 C10.2 | 47.14,45.71 47.14,46.35 | 47.14,44.44 47.14,45.71 | 47.14,42.38 47.14,44.44 | 47.14,41.9 47.14,42.22 47.14,42.38 | 47.14,38.6 47.14,39.05 47.14,41.9 | 47.14,38.6 IC2.39 | 47.14,37.95 47.14,38.6 | 47.14,42.38 47.14,42.5 IC2.33 43.3,42.5 43.65,42.06 C11.2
